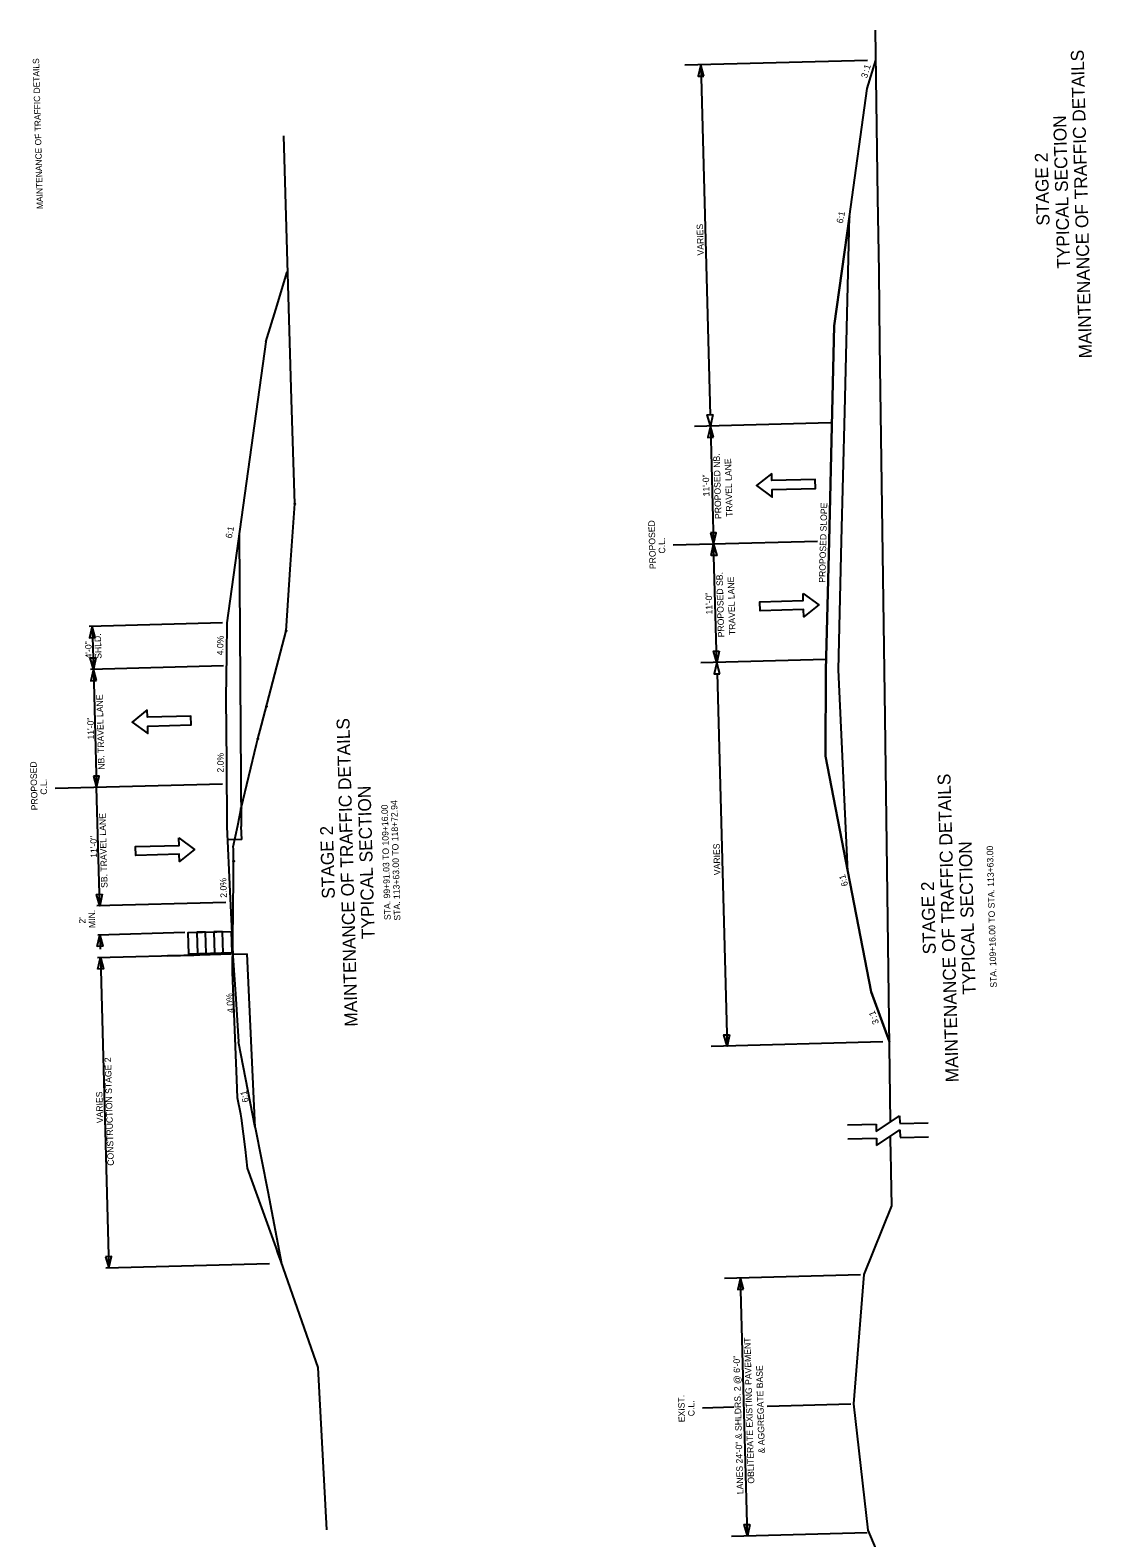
# Model space of a CAD drawing. Extents: x 1930579 to 1931594, y 596452 to 598557.
import ezdxf

# ---------------------------------------------------------------- set-up
doc = ezdxf.new("R2010")
doc.units = 0
for name, color, linetype in [('Default', 7, 'Continuous'), ('Level 1', 7, 'Continuous'), ('R_Annotation', 7, 'Continuous'), ('R_Border', 7, 'Continuous'), ('R_Dimension', 7, 'Continuous'), ('R_Exist Surface', 7, 'Continuous'), ('R_Fin Surface', 7, 'Continuous'), ('R_Horz Alg', 7, 'Continuous'), ('R_Horz Alg Annot', 7, 'Continuous'), ('R_MOT', 7, 'Continuous'), ('R_Proposed Const Limits_Fill', 7, 'Continuous'), ('R_Proposed Road_Lane', 7, 'Continuous'), ('R_Xsect Slope', 7, 'Continuous')]:
    doc.layers.add(name, color=color, linetype=linetype)

msp = doc.modelspace()

# ---------------------------------------------------------------- linework, layer by layer
for centre in [(1930852, 598116.8), (1930843.9, 597998.7), (1930825.6, 597928.2), (1930817.5, 597898.2), (1930802.2, 597833.6), (1930795.1, 597784.3)]:
    msp.add_circle(centre, 0.5)
at = {"layer": 'Default'}
for points in [[(1931295.7, 598145.1), (1931281.7, 598133.7), (1931296.3, 598123.1), (1931296.1, 598130), (1931336.6, 598131.1), (1931336.3, 598139.3), (1931295.9, 598138.3)], [(1931324.9, 598033.5), (1931339.5, 598022.9), (1931325.5, 598011.5), (1931325.3, 598018.4), (1931284.9, 598017.3), (1931284.6, 598025.6), (1931325.1, 598026.7)], [(1930714.7, 597925.2), (1930700.7, 597913.8), (1930715.3, 597903.2), (1930715.1, 597910.1), (1930755.6, 597911.2), (1930755.3, 597919.4), (1930714.9, 597918.3)], [(1930744.1, 597806), (1930758.7, 597795.3), (1930744.7, 597784), (1930744.5, 597790.8), (1930704.1, 597789.7), (1930703.8, 597798), (1930744.3, 597799.1)]]:
    msp.add_lwpolyline(points, close=True, dxfattribs=at)
at = {"layer": 'Level 1'}
for p, q in [((1930763.5, 597697.1), (1930733.5, 597696.3)), ((1930733.5, 597696.3), (1930757.9, 597697))]:
    msp.add_line(p, q, dxfattribs=at)
at = {"layer": 'R_Annotation'}
for q in [(1930807.6, 597698.3), (1930799.7, 597616.4)]:
    msp.add_line((1930815.2, 597536.7), q, dxfattribs=at)
msp.add_lwpolyline([(1930794.3, 597698), (1930794.3, 597696.3), (1930797, 597656.3), (1930799.7, 597616.4)], dxfattribs=at)
at = {"layer": 'R_Border'}
for p, q in [((1931366.4, 597539), (1931392.8, 597539.7)), ((1931366.4, 597539), (1931392.8, 597539.7)), ((1931392.8, 597539.7), (1931393, 597532.8)), ((1931392.8, 597539.7), (1931393, 597532.8)), ((1931393, 597532.8), (1931414.7, 597547.5)), ((1931393, 597532.8), (1931414.7, 597547.5)), ((1931414.7, 597547.5), (1931414.9, 597540.6)), ((1931414.7, 597547.5), (1931414.9, 597540.6)), ((1931414.9, 597540.3), (1931441.3, 597541)), ((1931414.9, 597540.3), (1931441.3, 597541)), ((1931366.7, 597526.1), (1931393.1, 597526.8)), ((1931393.1, 597526.8), (1931393.3, 597519.9)), ((1931393.3, 597519.9), (1931415.1, 597534.6)), ((1931415.1, 597534.6), (1931415.3, 597527.7)), ((1931415.3, 597527.4), (1931441.7, 597528.1))]:
    msp.add_line(p, q, dxfattribs=at)
at = {"layer": 'R_Dimension'}
for p, q in [((1931384.9, 598529.2), (1931214.8, 598524.6)), ((1931229.7, 598525), (1931238.4, 598199.1)), ((1931350.3, 598192.1), (1931223.9, 598188.7)), ((1931238.7, 598189.1), (1931241.7, 598079.2)), ((1931244.6, 597969.2), (1931241.7, 598079.2)), ((1930784.7, 598006.1), (1930660.8, 598002.8)), ((1930663.5, 598002.9), (1930664.6, 597962.9)), ((1930785.8, 597966.1), (1930661.9, 597962.8)), ((1930664.6, 597962.9), (1930667.5, 597852.9)), ((1931345.9, 597971.9), (1931229.8, 597968.8)), ((1931244.9, 597959.2), (1931254.2, 597612.4)), ((1930670.5, 597743), (1930667.5, 597852.9)), ((1930787.7, 597746.1), (1930667.8, 597742.9)), ((1930749.8, 597717.9), (1930668.6, 597715.7)), ((1930670.6, 597715.7), (1930670.9, 597702.5)), ((1930671.1, 597694.7), (1930678.9, 597406)), ((1931399.2, 597616.3), (1931239.3, 597612)), ((1930828.4, 597410), (1930676.3, 597405.9)), ((1931378.3, 597399.7), (1931251.8, 597396.3)), ((1931273.1, 597156.8), (1931266.7, 597396.7)), ((1931384.7, 597159.8), (1931258.3, 597156.4))]:
    msp.add_line(p, q, dxfattribs=at)
for points in [[(1931232.6, 598514.5), (1931229.7, 598525), (1931227.3, 598514.4)], [(1931241.1, 598199.8), (1931238.7, 598189.2), (1931235.8, 598199.6)], [(1931241.6, 598178.7), (1931238.7, 598189.1), (1931236.3, 598178.5)], [(1931238.7, 598089.7), (1931241.7, 598079.2), (1931244, 598089.8)], [(1931239.3, 598068.6), (1931241.7, 598079.2), (1931244.6, 598068.7)], [(1930666.4, 597992.4), (1930663.5, 598002.9), (1930661.1, 597992.2)], [(1930666.9, 597973.5), (1930664.6, 597962.9), (1930661.6, 597973.4)], [(1931247, 597979.8), (1931244.6, 597969.2), (1931241.7, 597979.7)], [(1930667.5, 597952.4), (1930664.6, 597962.9), (1930662.2, 597952.2)], [(1931247.5, 597958.7), (1931244.6, 597969.2), (1931242.2, 597958.6)], [(1930664.6, 597863.4), (1930667.5, 597852.9), (1930669.9, 597863.5)], [(1930672.8, 597753.6), (1930670.5, 597743), (1930667.5, 597753.4)], [(1930668.2, 597705.1), (1930670.6, 597715.7), (1930673.5, 597705.2)], [(1930668.8, 597684), (1930671.1, 597694.7), (1930674.1, 597684.2)], [(1931256.5, 597623), (1931254.2, 597612.4), (1931251.3, 597622.9)], [(1930676, 597416.5), (1930678.9, 597406), (1930681.3, 597416.6)], [(1931269.6, 597386.2), (1931266.7, 597396.7), (1931264.3, 597386.1)], [(1931275.5, 597167.4), (1931273.1, 597156.8), (1931270.2, 597167.3)]]:
    msp.add_lwpolyline(points, close=True, dxfattribs=at)
msp.add_lwpolyline([(1930792.9, 597697.9), (1930763.7, 597697.1), (1930668.5, 597694.6)], dxfattribs=at)
at = {"layer": 'R_Exist Surface'}
for points in [[(1931406.2, 597541.8), (1931401.2, 597918), (1931396.4, 598265.9), (1931395.6, 598332.6), (1931394.6, 598401.3), (1931392.3, 598557.3)], [(1930798, 597581.2), (1930794.1, 597681.1), (1930794.9, 597769.1), (1930795.1, 597784.3), (1930794.9, 597796), (1930794.8, 597797.7), (1930799, 597817.7), (1930802.2, 597833.6), (1930816.5, 597893.3), (1930817.5, 597898.2), (1930821, 597910.8), (1930843.9, 597998.7), (1930847.9, 598060.4), (1930852, 598116.8), (1930848.9, 598213.8), (1930841.7, 598459)], [(1930881.9, 597162.6), (1930873.8, 597313.4), (1930839.2, 597411.7), (1930836.6, 597419.3), (1930834.6, 597425.1), (1930808.1, 597498.7), (1930806, 597516.3), (1930802.4, 597545.3), (1930801.8, 597549.1), (1930798.6, 597564.4), (1930798, 597581.2)], [(1931417.2, 597043.6), (1931416.1, 597089.2), (1931385.6, 597162.3), (1931372.1, 597279.5), (1931381.9, 597399.8), (1931407.4, 597463.7), (1931406.9, 597495.6), (1931406.8, 597501), (1931406.7, 597509), (1931406.4, 597528.7)]]:
    msp.add_lwpolyline(points, dxfattribs=at)
at = {"layer": 'R_Fin Surface'}
for points in [[(1931368.1, 598383.9), (1931384.7, 598503.2)], [(1931366.6, 597774.8), (1931388.3, 597663)]]:
    msp.add_lwpolyline(points, dxfattribs=at)
at = {"layer": 'R_Horz Alg'}
for p, q in [((1931240.8, 598079.2), (1931204.2, 598078.2)), ((1931338.2, 598081.8), (1931240.8, 598079.2)), ((1930784.8, 597856.1), (1930629, 597851.9)), ((1931260.4, 597276.5), (1931231.4, 597275.7)), ((1931369.5, 597279.4), (1931291.6, 597277.3))]:
    msp.add_line(p, q, dxfattribs=at)
at = {"layer": 'R_Horz Alg Annot'}
for points in [[(1931405.2, 597616.4), (1931388.3, 597663), (1931366.6, 597774.8), (1931345.8, 597881.9), (1931346.1, 597961.9), (1931349.1, 598082.1), (1931352, 598202.2), (1931354, 598282.3), (1931368.1, 598383.9), (1931384.7, 598503.2), (1931392.7, 598529.4)], [(1930815.2, 597536.7), (1930826.8, 597477.1), (1930839.7, 597410.3)]]:
    msp.add_lwpolyline(points, dxfattribs=at)
at = {"layer": 'R_MOT'}
for points in [[(1930792.8, 597719), (1930793.3, 597699), (1930753.4, 597697.9), (1930752.8, 597717.9)], [(1930760.8, 597718.2), (1930761.4, 597698.2), (1930769.4, 597698.4), (1930768.8, 597718.4)], [(1930776.8, 597718.6), (1930777.4, 597698.6), (1930785.3, 597698.8), (1930784.8, 597718.8)]]:
    msp.add_lwpolyline(points, close=True, dxfattribs=at)
at = {"layer": 'R_Proposed Const Limits_Fill'}
for points in [[(1931384.7, 598503.2), (1931392.7, 598529.4)], [(1931388.3, 597663), (1931405.2, 597616.4)]]:
    msp.add_lwpolyline(points, dxfattribs=at)
at = {"layer": 'R_Proposed Road_Lane'}
for p, q in [((1930825.2, 598267.3), (1930788.8, 598006.2)), ((1930808.4, 598146.8), (1930788.8, 598006.2)), ((1930800.2, 598087.9), (1930802.1, 597816.5)), ((1930802.6, 597804.5), (1930802.1, 597816.5)), ((1930802.6, 597804.5), (1930789.3, 597804.1)), ((1930794.3, 597698), (1930807.6, 597698.3))]:
    msp.add_line(p, q, dxfattribs=at)
msp.add_lwpolyline([(1931363.7, 598202.5), (1931368.1, 598383.9), (1931354, 598282.3), (1931352, 598202.2), (1931349.1, 598082.1), (1931346.1, 597961.9), (1931345.8, 597881.9), (1931366.6, 597774.8), (1931357.8, 597962.3), (1931360.7, 598082.4)], close=True, dxfattribs=at)
for points in [[(1930825.2, 598267.3), (1930834.4, 598297.6), (1930845, 598332.5)], [(1930788.8, 598006.2), (1930788.4, 597976.2), (1930787.9, 597936.2), (1930788.3, 597876.2), (1930788.7, 597816.2), (1930791.5, 597756.2), (1930794.3, 597698)]]:
    msp.add_lwpolyline(points, dxfattribs=at)

# ---------------------------------------------------------------- texts
at = {"layer": 'R_Annotation'}
for s, height, p in [('MAINTENANCE OF TRAFFIC DETAILS', 12, (1931593.7, 598252.2)), ('TYPICAL SECTION', 12, (1931573.4, 598335.6)), ('STAGE 2 ', 12, (1931554.3, 598375.7)), ('VARIES', 6, (1931232.6, 598347.8)), ('PROPOSED NB.', 6, (1931249, 598102.7)), ('TRAVEL LANE', 6, (1931259.4, 598104.7)), ('11\'-0"', 6, (1931237.9, 598123.8)), ('PROPOSED', 6, (1931188.1, 598056.1)), ('C.L.', 6, (1931196.7, 598070.6)), ('PROPOSED SB.', 6, (1931251.7, 597992.7)), ('TRAVEL LANE', 6, (1931262.1, 597994.7)), ('11\'-0"', 6, (1931240.6, 598013.9)), ('4\'-0" ', 6, (1930663.2, 597973)), ('SHLD.', 6, (1930672.2, 597972.7)), ('NB. TRAVEL LANE', 6, (1930675.1, 597869.5)), ('11\'-0"', 6, (1930665.3, 597897.6)), ('MAINTENANCE OF TRAFFIC DETAILS', 12, (1930910.5, 597630.6)), ('PROPOSED', 6, (1930612.9, 597831.8)), ('MAINTENANCE OF TRAFFIC DETAILS', 12, (1931469.7, 597578.9)), ('C.L.', 6, (1930621.5, 597846.3)), ('TYPICAL SECTION ', 12, (1930926.3, 597712.1)), ('STA. 99+91.03 TO 109+16.00', 6, (1930941.3, 597729.7)), ('STA. 113+63.00 TO 118+72.94', 6, (1930950.3, 597729.2)), ('SB. TRAVEL LANE', 6, (1930677.8, 597759.6)), ('11\'-0"', 6, (1930668.1, 597787.6)), ('STAGE 2', 12, (1930889.3, 597749.6)), ('VARIES', 6, (1931248.1, 597771.5)), ('TYPICAL SECTION ', 12, (1931485.5, 597660.4)), ('STA. 109+16.00 TO STA. 113+63.00', 6, (1931505.2, 597666.8)), ('STAGE 2', 12, (1931448.5, 597697.9)), ('MIN.', 6, (1930666.4, 597722.3)), ("2'", 6, (1930657.3, 597726.4)), ('CONSTRUCTION STAGE 2', 6, (1930683.7, 597501.2)), ('VARIES', 6, (1930673.7, 597540.8)), ('OBLITERATE EXISTING PAVEMENT', 6, (1931279.6, 597205.5)), ('LANES 24\'-0" & SHLDRS. 2 @ 6\'-0"', 6, (1931269.4, 597195.7)), ('& AGGREGATE BASE', 6, (1931289.4, 597233.6)), ('EXIST.', 6, (1931215.1, 597262.6)), ('C.L.', 6, (1931224, 597268.2))]:
    msp.add_text(s, height=height, rotation=91.5377, dxfattribs=at).set_placement(p)
at = {"layer": 'R_Border'}
msp.add_text('MAINTENANCE OF TRAFFIC DETAILS', height=5.862, rotation=91.5377, dxfattribs=at).set_placement((1930617.8, 598391))
at = {"layer": 'R_Xsect Slope'}
for s, rotation, p in [('1', 73.1028, (1931386.8, 598520.2)), (':', 73.1028, (1931385.9, 598517.4)), ('3', 73.1028, (1931384.4, 598512.2)), ('6:1', 77.0989, (1931361.7, 598377.2)), ('PROPOSED SLOPE', 88.5946, (1931345.6, 598043.3)), ('6:1', 77.0989, (1930793.2, 598084.2)), ('4.0%', 88.8445, (1930785.4, 597975.8)), ('2.0%', 89.9893, (1930785.8, 597866.8)), ('2.0%', 92.2809, (1930788.9, 597750.5)), ('6:1', 105.9765, (1931366.9, 597761.9)), ('4.0%', 95.0822, (1930795.5, 597643.5)), ('1', 109.9726, (1931392.9, 597641.7)), (':', 109.9726, (1931393.9, 597638.9)), ('3', 109.9726, (1931395.7, 597633.8)), ('6:1', 101.6262, (1930809.2, 597560.6))]:
    msp.add_text(s, height=6, rotation=rotation, dxfattribs=at).set_placement(p)

doc.saveas('drawing.dxf')
